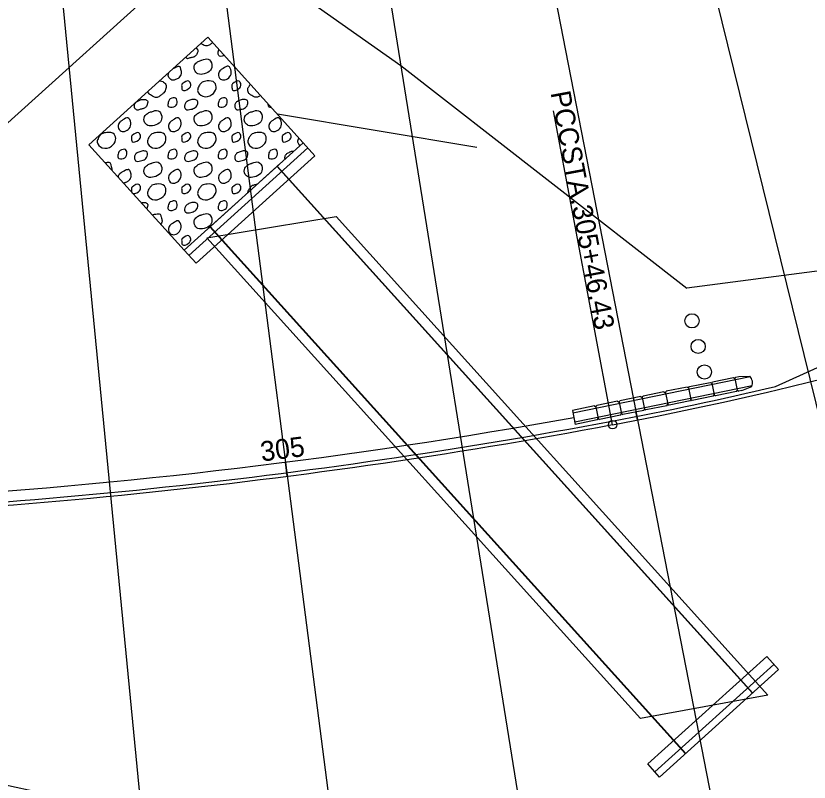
# Model space of a CAD drawing. Extents: x 153902 to 157473, y 413085 to 414252.
# Drawn here: x 154263.6 to 154375.4, y 413658.2 to 413766.1 of the extents above; entities that cross this region are included whole.
import ezdxf

# ---------------------------------------------------------------- set-up
doc = ezdxf.new("R2010")
doc.units = 0
for name, color, linetype in [('DR_X_Ditch', 7, 'Continuous'), ('DR_X_Headwall', 7, 'Continuous'), ('GE_P_Alignment', 7, 'Continuous'), ('GE_P_Alignment_100_Cardinal_Points', 7, 'Continuous'), ('PF_X_Ground_Line', 7, 'Continuous'), ('PV_X_Driveway', 7, 'Continuous'), ('PV_X_Text', 7, 'Continuous'), ('SV_X_Mon_Cells_Found', 7, 'Continuous'), ('SV_X_Text', 7, 'Continuous'), ('UT_X_Electric_Cells', 7, 'Continuous')]:
    doc.layers.add(name, color=color, linetype=linetype)

msp = doc.modelspace()

# ---------------------------------------------------------------- linework, layer by layer
at = {"layer": 'DR_X_Ditch'}
for p, q in [((154290.5, 413734.89), (154308.71, 413737.85)), ((154369.55, 413670.44), (154308.71, 413737.85)), ((154351.63, 413667.16), (154290.5, 413734.89)), ((154369.55, 413670.44), (154351.63, 413667.16))]:
    msp.add_line(p, q, dxfattribs=at)
at = {"layer": 'DR_X_Headwall'}
for p, q in [((154273.9, 413747.98), (154290.67, 413763.12)), ((154290.67, 413763.12), (154304.07, 413748.27)), ((154273.9, 413747.98), (154287.3, 413733.14))]:
    msp.add_line(p, q, dxfattribs=at)
for points in [[(154288.98, 413761.59), (154289.04, 413761.57), (154289.09, 413761.53), (154289.15, 413761.47), (154289.27, 413761.35), (154289.25, 413761.19), (154289.22, 413761.07), (154289.16, 413760.86), (154289.08, 413760.64), (154288.87, 413760.47), (154288.67, 413760.31), (154288.46, 413760.28), (154288.25, 413760.23), (154288.02, 413760.18), (154287.76, 413760.05), (154287.54, 413760.25), (154287.53, 413760.25), (154287.52, 413760.26), (154287.52, 413760.27)], [(154291.32, 413762.39), (154291.29, 413762.36), (154291.25, 413762.33), (154291.22, 413762.3), (154290.84, 413761.97), (154290.31, 413761.85), (154289.92, 413762.08), (154289.84, 413762.12), (154289.76, 413762.17), (154289.69, 413762.23)], [(154292.94, 413760.59), (154292.93, 413760.59), (154292.92, 413760.58), (154292.91, 413760.57), (154292.7, 413760.41), (154292.26, 413760.44), (154292.14, 413760.68), (154292.06, 413760.84), (154292.1, 413761.02), (154292.14, 413761.18), (154292.16, 413761.25), (154292.18, 413761.33), (154292.21, 413761.41)], [(154285.85, 413758.76), (154286.05, 413758.85), (154286.26, 413758.94), (154286.46, 413759.03), (154286.7, 413759.13), (154286.82, 413758.6), (154286.88, 413758.35), (154286.93, 413758.09), (154286.86, 413757.8), (154286.65, 413757.54), (154286.45, 413757.3), (154286.23, 413757.19), (154285.99, 413757.12), (154285.79, 413757.06), (154285.55, 413757.05), (154285.36, 413757.24), (154285.14, 413757.46), (154285.05, 413757.72), (154285.1, 413757.95), (154285.11, 413758.01), (154285.12, 413758.07), (154285.15, 413758.13)], [(154283.9, 413757), (154284.1, 413756.98), (154284.31, 413756.89), (154284.52, 413756.71), (154284.79, 413756.49), (154284.81, 413756.16), (154284.74, 413755.91), (154284.65, 413755.59), (154284.45, 413755.3), (154284.14, 413755.04), (154283.76, 413754.71), (154283.24, 413754.58), (154282.85, 413754.82), (154282.58, 413754.97), (154282.3, 413755.2), (154282.19, 413755.46)], [(154298.09, 413754.89), (154297.74, 413754.68), (154297.32, 413754.62), (154296.99, 413754.82), (154296.68, 413755), (154296.34, 413755.28), (154296.28, 413755.61), (154296.24, 413755.82), (154296.35, 413756.06), (154296.47, 413756.25), (154296.53, 413756.33), (154296.58, 413756.42), (154296.64, 413756.5)], [(154280.61, 413754.04), (154280.76, 413754.11), (154280.9, 413754.19), (154281.05, 413754.26), (154281.24, 413754.35), (154281.45, 413754.37), (154281.65, 413754.37), (154281.8, 413754.38), (154281.94, 413754.34), (154282.08, 413754.21), (154282.2, 413754.09), (154282.18, 413753.93), (154282.14, 413753.81), (154282.08, 413753.6), (154282.01, 413753.38), (154281.8, 413753.21), (154281.6, 413753.05), (154281.39, 413753.02), (154281.18, 413752.97), (154280.95, 413752.92), (154280.69, 413752.79), (154280.47, 413752.98), (154280.33, 413753.11), (154280.3, 413753.27), (154280.3, 413753.42), (154280.3, 413753.55), (154280.32, 413753.71), (154280.4, 413753.82), (154280.43, 413753.86), (154280.46, 413753.89), (154280.49, 413753.93)], [(154299.61, 413753.21), (154299.44, 413753.22), (154299.28, 413753.29), (154299.21, 413753.42), (154299.17, 413753.51), (154299.16, 413753.6), (154299.17, 413753.69)], [(154303.63, 413747.88), (154303.49, 413748.02), (154303.39, 413748.18), (154303.35, 413748.35), (154303.32, 413748.53), (154303.4, 413748.73), (154303.49, 413748.9)], [(154301.77, 413746.75), (154301.93, 413746.83), (154302.1, 413746.92), (154302.27, 413747), (154302.42, 413747.08), (154302.61, 413747.1), (154302.78, 413747.11)], [(154301.53, 413745.98), (154301.52, 413746.04), (154301.51, 413746.1), (154301.52, 413746.15), (154301.52, 413746.29), (154301.54, 413746.44), (154301.62, 413746.55), (154301.67, 413746.62), (154301.72, 413746.68), (154301.77, 413746.75)], [(154276.18, 413745.46), (154276.31, 413745.48), (154276.43, 413745.5), (154276.56, 413745.52), (154276.86, 413745.56), (154277, 413745.05), (154277.08, 413744.76), (154277.11, 413744.66), (154277.12, 413744.55), (154277.11, 413744.43)], [(154296.91, 413742.27), (154297.15, 413742.33), (154297.38, 413742.39), (154297.62, 413742.45), (154297.62, 413742.45), (154297.62, 413742.45), (154297.62, 413742.45)], [(154296.28, 413741.24), (154296.29, 413741.4), (154296.38, 413741.58), (154296.47, 413741.73), (154296.56, 413741.86), (154296.64, 413742), (154296.75, 413742.11), (154296.8, 413742.16), (154296.86, 413742.22), (154296.91, 413742.27)], [(154281.28, 413739.81), (154281.4, 413739.84), (154281.53, 413739.85), (154281.65, 413739.85), (154281.8, 413739.86), (154281.94, 413739.82), (154282.08, 413739.69), (154282.2, 413739.57), (154282.18, 413739.41), (154282.14, 413739.28), (154282.11, 413739.18), (154282.08, 413739.08), (154282.03, 413738.98)], [(154282.8, 413738.12), (154283.08, 413738.17), (154283.36, 413738.22), (154283.63, 413738.26), (154283.94, 413738.3), (154284.08, 413737.78), (154284.15, 413737.5), (154284.21, 413737.27), (154284.18, 413737), (154284.02, 413736.77)]]:
    msp.add_open_spline(points, degree=3, dxfattribs=at)
for points in [[(154289.8, 413759.89), (154290.71, 413760.04), (154291.22, 413759.28), (154291.03, 413758.47), (154290.14, 413757.97), (154289.26, 413757.97), (154288.86, 413758.33), (154288.79, 413759.22), (154289.2, 413759.64), (154289.65, 413759.86), (154289.81, 413759.9)], [(154292.83, 413758.73), (154293.53, 413759.03), (154293.95, 413758.35), (154293.72, 413757.54), (154293.06, 413757.12), (154292.44, 413757.24), (154292.17, 413757.95), (154292.46, 413758.49), (154292.83, 413758.73)], [(154287.04, 413756.54), (154287.99, 413756.92), (154288.24, 413756.49), (154287.94, 413755.88), (154287.04, 413755.71), (154286.97, 413756.19), (154286.97, 413756.43), (154287.04, 413756.54)], [(154289.84, 413756.79), (154290.55, 413756.98), (154291.59, 413756.71), (154291.81, 413755.91), (154291.22, 413755.04), (154289.92, 413754.82), (154289.21, 413755.61), (154289.4, 413756.25), (154289.68, 413756.63), (154289.84, 413756.79)], [(154294.11, 413756.54), (154295.06, 413756.92), (154295.31, 413756.49), (154295.02, 413755.88), (154294.12, 413755.71), (154294.04, 413756.19), (154294.05, 413756.43), (154294.11, 413756.54)], [(154285.35, 413754.44), (154286.11, 413754.55), (154286.32, 413753.9), (154285.84, 413753.31), (154285.07, 413753.42), (154285.07, 413753.91), (154285.19, 413754.24), (154285.35, 413754.44)], [(154287.62, 413754.01), (154288.12, 413754.26), (154288.73, 413754.37), (154289.15, 413754.21), (154289.22, 413753.81), (154288.87, 413753.21), (154288.25, 413752.97), (154287.54, 413752.98), (154287.37, 413753.42), (154287.48, 413753.82), (154287.62, 413754.01)], [(154292.42, 413754.44), (154293.18, 413754.55), (154293.39, 413753.9), (154292.91, 413753.31), (154292.14, 413753.42), (154292.14, 413753.91), (154292.26, 413754.24), (154292.42, 413754.44)], [(154294.7, 413754.01), (154295.2, 413754.26), (154295.8, 413754.37), (154296.22, 413754.21), (154296.29, 413753.81), (154295.95, 413753.21), (154295.32, 413752.97), (154294.62, 413752.98), (154294.44, 413753.42), (154294.55, 413753.82), (154294.7, 413754.01)], [(154282.73, 413752.63), (154283.63, 413752.78), (154284.15, 413752.02), (154283.96, 413751.21), (154283.07, 413750.7), (154282.19, 413750.71), (154281.79, 413751.07), (154281.72, 413751.96), (154282.13, 413752.38), (154282.58, 413752.6), (154282.74, 413752.63)], [(154289.8, 413752.63), (154290.71, 413752.78), (154291.22, 413752.02), (154291.03, 413751.21), (154290.14, 413750.7), (154289.26, 413750.71), (154288.86, 413751.07), (154288.79, 413751.96), (154289.2, 413752.38), (154289.65, 413752.6), (154289.81, 413752.63)], [(154296.87, 413752.63), (154297.78, 413752.78), (154298.3, 413752.02), (154298.1, 413751.21), (154297.21, 413750.7), (154296.33, 413750.71), (154295.93, 413751.07), (154295.86, 413751.96), (154296.27, 413752.38), (154296.72, 413752.6), (154296.89, 413752.63)], [(154278.69, 413751.47), (154279.39, 413751.77), (154279.8, 413751.09), (154279.58, 413750.28), (154278.91, 413749.86), (154278.29, 413749.97), (154278.03, 413750.69), (154278.32, 413751.23), (154278.69, 413751.47)], [(154285.76, 413751.47), (154286.46, 413751.77), (154286.88, 413751.09), (154286.65, 413750.28), (154285.99, 413749.86), (154285.36, 413749.97), (154285.1, 413750.69), (154285.39, 413751.23), (154285.76, 413751.47)], [(154292.83, 413751.47), (154293.53, 413751.77), (154293.95, 413751.09), (154293.72, 413750.28), (154293.06, 413749.86), (154292.44, 413749.97), (154292.17, 413750.69), (154292.46, 413751.23), (154292.83, 413751.47)], [(154299.9, 413751.47), (154300.6, 413751.77), (154301.02, 413751.09), (154300.8, 413750.28), (154300.13, 413749.86), (154299.51, 413749.97), (154299.24, 413750.69), (154299.53, 413751.23), (154299.9, 413751.47)], [(154275.7, 413749.53), (154276.41, 413749.71), (154277.45, 413749.45), (154277.66, 413748.65), (154277.07, 413747.78), (154275.78, 413747.55), (154275.07, 413748.35), (154275.26, 413748.99), (154275.53, 413749.37), (154275.7, 413749.53)], [(154279.97, 413749.28), (154280.92, 413749.66), (154281.17, 413749.22), (154280.87, 413748.62), (154279.97, 413748.45), (154279.89, 413748.93), (154279.9, 413749.17), (154279.97, 413749.28)], [(154282.77, 413749.53), (154283.48, 413749.71), (154284.52, 413749.45), (154284.74, 413748.65), (154284.14, 413747.78), (154282.85, 413747.55), (154282.14, 413748.35), (154282.33, 413748.99), (154282.61, 413749.37), (154282.77, 413749.53)], [(154287.04, 413749.28), (154287.99, 413749.66), (154288.24, 413749.22), (154287.94, 413748.62), (154287.04, 413748.45), (154286.97, 413748.93), (154286.97, 413749.17), (154287.04, 413749.28)], [(154289.84, 413749.53), (154290.55, 413749.71), (154291.59, 413749.45), (154291.81, 413748.65), (154291.22, 413747.78), (154289.92, 413747.55), (154289.21, 413748.35), (154289.4, 413748.99), (154289.68, 413749.37), (154289.84, 413749.53)], [(154294.11, 413749.28), (154295.06, 413749.66), (154295.31, 413749.22), (154295.02, 413748.62), (154294.12, 413748.45), (154294.04, 413748.93), (154294.05, 413749.17), (154294.11, 413749.28)], [(154296.91, 413749.53), (154297.62, 413749.71), (154298.66, 413749.45), (154298.88, 413748.65), (154298.29, 413747.78), (154296.99, 413747.55), (154296.28, 413748.35), (154296.47, 413748.99), (154296.75, 413749.37), (154296.91, 413749.53)], [(154301.18, 413749.28), (154302.13, 413749.66), (154302.39, 413749.22), (154302.09, 413748.62), (154301.19, 413748.45), (154301.11, 413748.93), (154301.12, 413749.17), (154301.18, 413749.28)], [(154278.28, 413747.18), (154279.04, 413747.29), (154279.25, 413746.64), (154278.77, 413746.05), (154278, 413746.16), (154278, 413746.65), (154278.12, 413746.98), (154278.28, 413747.18)], [(154280.55, 413746.75), (154281.05, 413747), (154281.65, 413747.11), (154282.08, 413746.95), (154282.14, 413746.54), (154281.8, 413745.95), (154281.18, 413745.71), (154280.47, 413745.72), (154280.3, 413746.15), (154280.4, 413746.55), (154280.55, 413746.75)], [(154285.35, 413747.18), (154286.11, 413747.29), (154286.32, 413746.64), (154285.84, 413746.05), (154285.07, 413746.16), (154285.07, 413746.65), (154285.19, 413746.98), (154285.35, 413747.18)], [(154287.62, 413746.75), (154288.12, 413747), (154288.73, 413747.11), (154289.15, 413746.95), (154289.22, 413746.54), (154288.87, 413745.95), (154288.25, 413745.71), (154287.54, 413745.72), (154287.37, 413746.15), (154287.48, 413746.55), (154287.62, 413746.75)], [(154292.42, 413747.18), (154293.18, 413747.29), (154293.39, 413746.64), (154292.91, 413746.05), (154292.14, 413746.16), (154292.14, 413746.65), (154292.26, 413746.98), (154292.42, 413747.18)], [(154294.7, 413746.75), (154295.2, 413747), (154295.8, 413747.11), (154296.22, 413746.95), (154296.29, 413746.54), (154295.95, 413745.95), (154295.32, 413745.71), (154294.62, 413745.72), (154294.44, 413746.15), (154294.55, 413746.55), (154294.7, 413746.75)], [(154299.49, 413747.18), (154300.26, 413747.29), (154300.46, 413746.64), (154299.98, 413746.05), (154299.21, 413746.16), (154299.22, 413746.65), (154299.33, 413746.98), (154299.49, 413747.18)], [(154282.73, 413745.37), (154283.63, 413745.52), (154284.15, 413744.76), (154283.96, 413743.95), (154283.07, 413743.44), (154282.19, 413743.45), (154281.79, 413743.8), (154281.72, 413744.69), (154282.13, 413745.12), (154282.58, 413745.34), (154282.74, 413745.37)], [(154289.8, 413745.37), (154290.71, 413745.52), (154291.22, 413744.76), (154291.03, 413743.95), (154290.14, 413743.44), (154289.26, 413743.45), (154288.86, 413743.8), (154288.79, 413744.69), (154289.2, 413745.12), (154289.65, 413745.34), (154289.81, 413745.37)], [(154296.87, 413745.37), (154297.78, 413745.52), (154298.3, 413744.76), (154298.1, 413743.95), (154297.21, 413743.44), (154296.33, 413743.45), (154295.93, 413743.8), (154295.86, 413744.69), (154296.27, 413745.12), (154296.72, 413745.34), (154296.89, 413745.37)], [(154278.02, 413743.42), (154278.03, 413743.43), (154278.04, 413743.5), (154278.12, 413743.72), (154278.2, 413743.86), (154278.26, 413743.92), (154278.32, 413743.97), (154278.41, 413744.03), (154278.5, 413744.09), (154278.69, 413744.2)], [(154278.69, 413744.2), (154279.39, 413744.51), (154279.41, 413744.51), (154279.43, 413744.52), (154279.47, 413744.52), (154279.55, 413744.48), (154279.67, 413744.3), (154279.75, 413744.05), (154279.78, 413743.93), (154279.79, 413743.88), (154279.8, 413743.83), (154279.81, 413743.78), (154279.82, 413743.73), (154279.82, 413743.63), (154279.79, 413743.42), (154279.71, 413743.22), (154279.65, 413743.12), (154279.62, 413743.07), (154279.6, 413743.04), (154279.58, 413743.02), (154279.54, 413742.98), (154279.5, 413742.94), (154279.43, 413742.86), (154279.26, 413742.74), (154279.09, 413742.66), (154279, 413742.62), (154278.94, 413742.6), (154278.91, 413742.59), (154278.85, 413742.58), (154278.79, 413742.57)], [(154285.76, 413744.2), (154286.46, 413744.51), (154286.88, 413743.83), (154286.65, 413743.02), (154285.99, 413742.59), (154285.36, 413742.71), (154285.1, 413743.43), (154285.39, 413743.97), (154285.76, 413744.2)], [(154292.83, 413744.2), (154293.53, 413744.51), (154293.95, 413743.83), (154293.72, 413743.02), (154293.06, 413742.59), (154292.44, 413742.71), (154292.17, 413743.43), (154292.46, 413743.97), (154292.83, 413744.2)], [(154279.97, 413742.01), (154280.92, 413742.4), (154281.17, 413741.96), (154280.87, 413741.36), (154279.97, 413741.19), (154279.89, 413741.67), (154279.9, 413741.91), (154279.97, 413742.01)], [(154282.77, 413742.27), (154283.48, 413742.45), (154284.52, 413742.19), (154284.74, 413741.38), (154284.14, 413740.51), (154282.85, 413740.29), (154282.14, 413741.09), (154282.33, 413741.73), (154282.61, 413742.11), (154282.77, 413742.27)], [(154287.04, 413742.01), (154287.99, 413742.4), (154288.24, 413741.96), (154287.94, 413741.36), (154287.04, 413741.19), (154286.97, 413741.67), (154286.97, 413741.91), (154287.04, 413742.01)], [(154289.84, 413742.27), (154290.55, 413742.45), (154291.59, 413742.19), (154291.81, 413741.38), (154291.22, 413740.51), (154289.92, 413740.29), (154289.21, 413741.09), (154289.4, 413741.73), (154289.68, 413742.11), (154289.84, 413742.27)], [(154294.11, 413742.01), (154295.06, 413742.4), (154295.31, 413741.96), (154295.02, 413741.36), (154294.12, 413741.19), (154294.04, 413741.67), (154294.05, 413741.91), (154294.11, 413742.01)], [(154285.35, 413739.92), (154286.11, 413740.03), (154286.32, 413739.38), (154285.84, 413738.79), (154285.07, 413738.9), (154285.07, 413739.39), (154285.19, 413739.72), (154285.35, 413739.92)], [(154292.42, 413739.92), (154293.18, 413740.03), (154293.39, 413739.38), (154292.91, 413738.79), (154292.14, 413738.9), (154292.14, 413739.39), (154292.26, 413739.72), (154292.42, 413739.92)], [(154287.62, 413739.49), (154288.12, 413739.74), (154288.73, 413739.85), (154289.15, 413739.69), (154289.22, 413739.28), (154288.87, 413738.69), (154288.25, 413738.45), (154287.54, 413738.46), (154287.37, 413738.89), (154287.48, 413739.29), (154287.62, 413739.49)], [(154289.8, 413738.11), (154290.71, 413738.26), (154291.22, 413737.5), (154291.03, 413736.69), (154290.14, 413736.18), (154289.26, 413736.19), (154288.86, 413736.54), (154288.79, 413737.43), (154289.2, 413737.86), (154289.65, 413738.08), (154289.81, 413738.11)], [(154285.76, 413736.94), (154286.46, 413737.25), (154286.88, 413736.57), (154286.65, 413735.76), (154285.99, 413735.33), (154285.36, 413735.45), (154285.1, 413736.17), (154285.39, 413736.71), (154285.76, 413736.94)], [(154287.04, 413734.75), (154287.99, 413735.14), (154288.24, 413734.7), (154287.94, 413734.1), (154287.04, 413733.93), (154286.97, 413734.41), (154286.97, 413734.65), (154287.04, 413734.75)]]:
    msp.add_spline(points, degree=3, dxfattribs=at)
at = {"layer": 'GE_P_Alignment'}
for centre, radius, start, end in [((154251.74, 414218.49), 518.89, 280.6558, 303.1023), ((154199.36, 414496.89), 802.17, 270.66569, 280.65583)]:
    msp.add_arc(centre, radius, start, end, dxfattribs=at)
at = {"layer": 'GE_P_Alignment_100_Cardinal_Points'}
msp.add_line((154347.69, 413708.55), (154339.37, 413752.77), dxfattribs=at)
msp.add_circle((154347.69, 413708.55), 0.6, dxfattribs=at)
at = {"layer": 'PF_X_Ground_Line'}
for p, q in [((154351.2, 413709.22), (154350.97, 413710.4)), ((154301.84, 413701.29), (154301.58, 413703.27))]:
    msp.add_line(p, q, dxfattribs=at)
at = {"layer": 'PV_X_Driveway'}
for p, q in [((154287.3, 413733.14), (154304.07, 413748.27)), ((154304.07, 413748.27), (154305.74, 413746.41)), ((154287.97, 413732.39), (154304.74, 413747.53)), ((154288.98, 413731.28), (154305.74, 413746.41)), ((154290.49, 413736.01), (154300.88, 413745.39)), ((154367.39, 413670.72), (154300.39, 413744.95)), ((154367.42, 413670.75), (154300.42, 413744.97)), ((154357.96, 413662.2), (154290.95, 413736.43)), ((154357.99, 413662.23), (154290.98, 413736.46)), ((154287.3, 413733.14), (154288.98, 413731.28)), ((154369.4, 413675.9), (154352.64, 413660.76)), ((154371.07, 413674.04), (154369.4, 413675.9)), ((154370.4, 413674.78), (154353.64, 413659.65)), ((154371.07, 413674.04), (154354.31, 413658.91)), ((154354.31, 413658.91), (154352.64, 413660.76))]:
    msp.add_line(p, q, dxfattribs=at)
at = {"layer": 'PV_X_Text'}
for p, q in [((154404.26, 413598.07), (154346.96, 413831.13)), ((154328.2, 413827), (154374.2, 413591.45)), ((154345.61, 413586.39), (154307.55, 413823.35)), ((154286.51, 413820.31), (154317.17, 413582.27)), ((154288.61, 413579.05), (154265.39, 413817.92))]:
    msp.add_line(p, q, dxfattribs=at)
at = {"layer": 'SV_X_Mon_Cells_Found'}
msp.add_line((154328.54, 413747.61), (154300.46, 413752.31), dxfattribs=at)
at = {"layer": 'SV_X_Text'}
for p, q in [((154370.63, 413713.92), (154443.19, 413746.82)), ((154342.09, 413710.23), (154367.06, 413715.32)), ((154358.52, 413713.92), (154361.45, 413714.51)), ((154361.45, 413714.51), (154361.65, 413714.38)), ((154361.65, 413714.38), (154361.78, 413714.58)), ((154361.78, 413714.58), (154364.72, 413715.18)), ((154364.72, 413715.18), (154364.92, 413715.05)), ((154364.92, 413715.05), (154365.05, 413715.25)), ((154364.92, 413715.05), (154365.25, 413713.42)), ((154365.05, 413715.25), (154365.47, 413715.33)), ((154365.47, 413715.33), (154366.99, 413715.39)), ((154367.33, 413714.01), (154342.35, 413708.92)), ((154358.19, 413713.85), (154355.25, 413713.25)), ((154358.19, 413713.85), (154358.39, 413713.72)), ((154358.39, 413713.72), (154358.52, 413713.92)), ((154358.39, 413713.72), (154358.72, 413712.09)), ((154361.65, 413714.38), (154361.98, 413712.75)), ((154365.12, 413713.22), (154365.25, 413713.42)), ((154365.25, 413713.42), (154365.45, 413713.29)), ((154365.87, 413713.37), (154365.45, 413713.29)), ((154365.87, 413713.37), (154367.29, 413713.92)), ((154351.66, 413712.52), (154348.72, 413711.92)), ((154351.66, 413712.52), (154351.85, 413712.39)), ((154351.85, 413712.39), (154351.98, 413712.58)), ((154351.85, 413712.39), (154352.19, 413710.75)), ((154354.92, 413713.18), (154351.98, 413712.58)), ((154354.92, 413713.18), (154355.12, 413713.05)), ((154355.12, 413713.05), (154355.25, 413713.25)), ((154355.12, 413713.05), (154355.45, 413711.42)), ((154361.85, 413712.56), (154358.91, 413711.96)), ((154361.85, 413712.56), (154361.98, 413712.75)), ((154361.98, 413712.75), (154362.18, 413712.62)), ((154365.12, 413713.22), (154362.18, 413712.62)), ((154345.12, 413711.18), (154342.02, 413710.55)), ((154345.12, 413711.18), (154345.32, 413711.05)), ((154345.32, 413711.05), (154345.45, 413711.25)), ((154348.39, 413711.85), (154345.45, 413711.25)), ((154348.39, 413711.85), (154348.59, 413711.72)), ((154348.59, 413711.72), (154348.72, 413711.92)), ((154348.59, 413711.72), (154348.92, 413710.09)), ((154355.32, 413711.22), (154352.38, 413710.62)), ((154355.32, 413711.22), (154355.45, 413711.42)), ((154355.45, 413711.42), (154355.65, 413711.29)), ((154358.59, 413711.89), (154355.65, 413711.29)), ((154358.59, 413711.89), (154358.72, 413712.09)), ((154358.72, 413712.09), (154358.91, 413711.96)), ((154342.02, 413710.55), (154342.42, 413708.59)), ((154345.32, 413711.05), (154345.65, 413709.42)), ((154348.79, 413709.89), (154348.92, 413710.09)), ((154348.92, 413710.09), (154349.12, 413709.96)), ((154352.06, 413710.56), (154349.12, 413709.96)), ((154352.06, 413710.56), (154352.19, 413710.75)), ((154352.19, 413710.75), (154352.38, 413710.62)), ((154345.52, 413709.23), (154342.42, 413708.59)), ((154345.52, 413709.23), (154345.65, 413709.42)), ((154345.65, 413709.42), (154345.85, 413709.29)), ((154348.79, 413709.89), (154345.85, 413709.29))]:
    msp.add_line(p, q, dxfattribs=at)
for centre in [(154358.87, 413723.18), (154359.74, 413719.57), (154360.62, 413715.97)]:
    msp.add_circle(centre, 1, dxfattribs=at)
for centre, radius, start, end in [((154366.06, 413714.43), 1.34, 337.3499, 45.7013), ((154251.74, 414218.49), 518.39, 280.6558, 283.2583), ((154199.36, 414496.89), 801.67, 271.26817, 280.65583), ((154199.36, 414496.89), 800.17, 273.4105, 280.28464)]:
    msp.add_arc(centre, radius, start, end, dxfattribs=at)
at = {"layer": 'UT_X_Electric_Cells'}
for points in [[(154249.36, 413737.82), (154255.7, 413745.02), (154291.76, 413777.57), (154317.86, 413759.14), (154358.14, 413727.79)], [(154202.4, 413670.72), (154326.58, 413643.87), (154381.35, 413615.96), (154411.04, 413642.76), (154403.51, 413708.45), (154396.28, 413732.77), (154358.14, 413727.79)]]:
    msp.add_lwpolyline(points, dxfattribs=at)

# ---------------------------------------------------------------- texts
at = {"layer": 'GE_P_Alignment_100_Cardinal_Points'}
for s, p in [('PCC', (154338.93, 413755.31)), (' STA. ', (154340.21, 413748.53)), ('305+46.43', (154341.96, 413739.24))]:
    msp.add_text(s, height=2.8, rotation=280.6558, dxfattribs=at).set_placement(p)
at = {"layer": 'PF_X_Ground_Line'}
msp.add_text('305', height=2.8, rotation=7.3398, dxfattribs=at).set_placement((154298.24, 413703.35))

doc.saveas('drawing.dxf')
